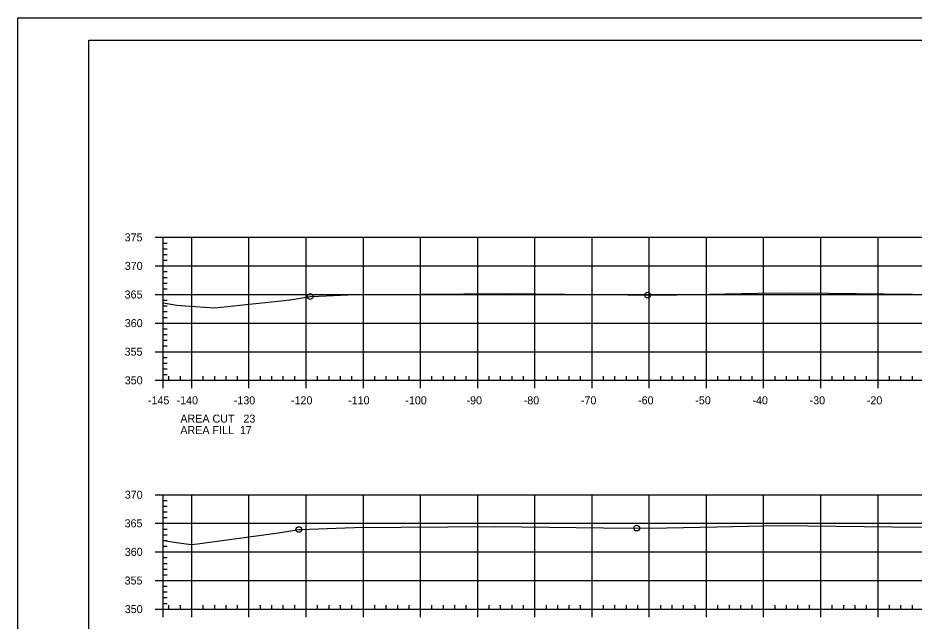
# Model space of a CAD drawing. Extents: x 1359801 to 1362404, y 372415 to 374228.
# Drawn here: x 1360417.1 to 1360573.8, y 373482.5 to 373588 of the extents above; entities that cross this region are included whole.
import ezdxf

# ---------------------------------------------------------------- set-up
doc = ezdxf.new("R2010")
doc.units = 0
for name, color, linetype in [('S_DRG_PT_SYM', 7, 'Continuous'), ('S_MAILBOX', 7, 'Continuous'), ('S_PRIMARY_CTL', 7, 'Continuous'), ('S_SHOULDER', 7, 'Continuous'), ('S_UTL_PT_SYM', 7, 'Continuous'), ('S_WATER_UTILITIES', 7, 'Continuous')]:
    doc.layers.add(name, color=color, linetype=linetype)

msp = doc.modelspace()

# ---------------------------------------------------------------- linework, layer by layer
at = {"layer": 'S_DRG_PT_SYM'}
for points in [[(1360442.53, 373538.12), (1360444.89, 373537.74), (1360446.4, 373537.61), (1360451.48, 373537.26), (1360463.66, 373538.54), (1360464.53, 373538.64), (1360464.75, 373538.68), (1360468.23, 373539.24), (1360469.76, 373539.31), (1360476.11, 373539.6), (1360480.42, 373539.62), (1360502.38, 373539.75), (1360518.08, 373539.6), (1360529.47, 373539.48), (1360546.58, 373539.81), (1360552.23, 373539.92), (1360558.81, 373539.84), (1360578.6, 373539.61)], [(1360442.53, 373496.58), (1360442.59, 373496.57), (1360445.29, 373496.19), (1360447.43, 373495.89), (1360448.54, 373496.04), (1360462.71, 373497.94), (1360465.91, 373498.45), (1360466.24, 373498.5), (1360466.53, 373498.51), (1360474.33, 373498.83), (1360475.99, 373498.84), (1360500.46, 373499.02), (1360519.54, 373498.82), (1360527.68, 373498.74), (1360539.36, 373498.99), (1360550.29, 373499.23), (1360570.05, 373498.99), (1360576.66, 373498.91)]]:
    msp.add_lwpolyline(points, dxfattribs=at)
at = {"layer": 'S_MAILBOX'}
for p, q in [((1360442.53, 373549.6), (1360732.53, 373549.6)), ((1360442.53, 373524.6), (1360442.53, 373549.6)), ((1360447.53, 373524.6), (1360447.53, 373549.6)), ((1360457.53, 373524.6), (1360457.53, 373549.6)), ((1360467.53, 373524.6), (1360467.53, 373549.6)), ((1360477.53, 373524.6), (1360477.53, 373549.6)), ((1360487.53, 373524.6), (1360487.53, 373549.6)), ((1360497.53, 373524.6), (1360497.53, 373549.6)), ((1360507.53, 373524.6), (1360507.53, 373549.6)), ((1360517.53, 373524.6), (1360517.53, 373549.6)), ((1360527.53, 373524.6), (1360527.53, 373549.6)), ((1360537.53, 373524.6), (1360537.53, 373549.6)), ((1360547.53, 373524.6), (1360547.53, 373549.6)), ((1360557.53, 373524.6), (1360557.53, 373549.6)), ((1360567.53, 373524.6), (1360567.53, 373549.6)), ((1360442.53, 373544.6), (1360732.53, 373544.6)), ((1360442.53, 373539.6), (1360732.53, 373539.6)), ((1360442.53, 373534.6), (1360732.53, 373534.6)), ((1360442.53, 373529.6), (1360732.53, 373529.6)), ((1360442.53, 373524.6), (1360732.53, 373524.6)), ((1360442.53, 373504.6), (1360732.53, 373504.6)), ((1360442.53, 373484.6), (1360442.53, 373504.6)), ((1360442.53, 373504.6), (1360732.53, 373504.6)), ((1360442.53, 373484.6), (1360442.53, 373504.6)), ((1360447.53, 373484.6), (1360447.53, 373504.6)), ((1360447.53, 373484.6), (1360447.53, 373504.6)), ((1360457.53, 373484.6), (1360457.53, 373504.6)), ((1360457.53, 373484.6), (1360457.53, 373504.6)), ((1360467.53, 373484.6), (1360467.53, 373504.6)), ((1360467.53, 373484.6), (1360467.53, 373504.6)), ((1360477.53, 373484.6), (1360477.53, 373504.6)), ((1360477.53, 373484.6), (1360477.53, 373504.6)), ((1360487.53, 373484.6), (1360487.53, 373504.6)), ((1360487.53, 373484.6), (1360487.53, 373504.6)), ((1360497.53, 373484.6), (1360497.53, 373504.6)), ((1360497.53, 373484.6), (1360497.53, 373504.6)), ((1360507.53, 373484.6), (1360507.53, 373504.6)), ((1360507.53, 373484.6), (1360507.53, 373504.6)), ((1360517.53, 373484.6), (1360517.53, 373504.6)), ((1360517.53, 373484.6), (1360517.53, 373504.6)), ((1360527.53, 373484.6), (1360527.53, 373504.6)), ((1360527.53, 373484.6), (1360527.53, 373504.6)), ((1360537.53, 373484.6), (1360537.53, 373504.6)), ((1360537.53, 373484.6), (1360537.53, 373504.6)), ((1360547.53, 373484.6), (1360547.53, 373504.6)), ((1360547.53, 373484.6), (1360547.53, 373504.6)), ((1360557.53, 373484.6), (1360557.53, 373504.6)), ((1360557.53, 373484.6), (1360557.53, 373504.6)), ((1360567.53, 373484.6), (1360567.53, 373504.6)), ((1360567.53, 373484.6), (1360567.53, 373504.6)), ((1360442.53, 373499.6), (1360732.53, 373499.6)), ((1360442.53, 373499.6), (1360732.53, 373499.6)), ((1360442.53, 373494.6), (1360732.53, 373494.6)), ((1360442.53, 373494.6), (1360732.53, 373494.6)), ((1360442.53, 373489.6), (1360732.53, 373489.6)), ((1360442.53, 373489.6), (1360732.53, 373489.6)), ((1360442.53, 373484.6), (1360732.53, 373484.6)), ((1360442.53, 373484.6), (1360732.53, 373484.6))]:
    msp.add_line(p, q, dxfattribs=at)
at = {"layer": 'S_SHOULDER'}
msp.add_line((1360417.13, 373587.95), (1360750.46, 373587.95), dxfattribs=at)
for points in [[(1360417.12, 373587.95), (1360750.46, 373587.95), (1360750.46, 373374.61), (1360417.12, 373374.61)], [(1360663.45, 373584.06), (1360663.45, 373574.18), (1360699.18, 373574.18), (1360699.18, 373571.26), (1360722.38, 373571.26), (1360722.38, 373546.93), (1360745.71, 373546.93), (1360745.71, 373378.6), (1360429.53, 373378.6), (1360429.53, 373584.06)]]:
    msp.add_lwpolyline(points, close=True, dxfattribs=at)
for centre in [(1360468.23, 373539.24), (1360527.25, 373539.5), (1360466.24, 373498.5), (1360525.33, 373498.76)]:
    msp.add_circle(centre, 0.5, dxfattribs=at)
at = {"layer": 'S_UTL_PT_SYM'}
for p, q in [((1360429.53, 373584.06), (1360745.71, 373584.06)), ((1360429.53, 373378.6), (1360429.53, 373584.06))]:
    msp.add_line(p, q, dxfattribs=at)
at = {"layer": 'S_WATER_UTILITIES'}
for p, q in [((1360441.13, 373549.6), (1360442.53, 373549.6)), ((1360442.53, 373524.6), (1360442.53, 373549.6)), ((1360442.53, 373548.6), (1360443.23, 373548.6)), ((1360442.53, 373547.6), (1360443.23, 373547.6)), ((1360442.53, 373546.6), (1360443.23, 373546.6)), ((1360442.53, 373545.6), (1360443.23, 373545.6)), ((1360441.13, 373544.6), (1360442.53, 373544.6)), ((1360442.53, 373543.6), (1360443.23, 373543.6)), ((1360442.53, 373542.6), (1360443.23, 373542.6)), ((1360442.53, 373541.6), (1360443.23, 373541.6)), ((1360442.53, 373540.6), (1360443.23, 373540.6)), ((1360441.13, 373539.6), (1360442.53, 373539.6)), ((1360442.53, 373538.6), (1360443.23, 373538.6)), ((1360442.53, 373537.6), (1360443.23, 373537.6)), ((1360442.53, 373536.6), (1360443.23, 373536.6)), ((1360441.13, 373534.6), (1360442.53, 373534.6)), ((1360442.53, 373535.6), (1360443.23, 373535.6)), ((1360442.53, 373533.6), (1360443.23, 373533.6)), ((1360442.53, 373532.6), (1360443.23, 373532.6)), ((1360442.53, 373531.6), (1360443.23, 373531.6)), ((1360441.13, 373529.6), (1360442.53, 373529.6)), ((1360442.53, 373530.6), (1360443.23, 373530.6)), ((1360442.53, 373528.6), (1360443.23, 373528.6)), ((1360442.53, 373527.6), (1360443.23, 373527.6)), ((1360442.53, 373526.6), (1360443.23, 373526.6)), ((1360442.53, 373525.6), (1360443.23, 373525.6)), ((1360442.53, 373524.6), (1360442.53, 373525.3)), ((1360443.53, 373524.6), (1360443.53, 373525.3)), ((1360445.53, 373524.6), (1360445.53, 373525.3)), ((1360449.53, 373524.6), (1360449.53, 373525.3)), ((1360451.53, 373524.6), (1360451.53, 373525.3)), ((1360453.53, 373524.6), (1360453.53, 373525.3)), ((1360455.53, 373524.6), (1360455.53, 373525.3)), ((1360459.53, 373524.6), (1360459.53, 373525.3)), ((1360461.53, 373524.6), (1360461.53, 373525.3)), ((1360463.53, 373524.6), (1360463.53, 373525.3)), ((1360465.53, 373524.6), (1360465.53, 373525.3)), ((1360469.53, 373524.6), (1360469.53, 373525.3)), ((1360471.53, 373524.6), (1360471.53, 373525.3)), ((1360473.53, 373524.6), (1360473.53, 373525.3)), ((1360475.53, 373524.6), (1360475.53, 373525.3)), ((1360479.53, 373524.6), (1360479.53, 373525.3)), ((1360481.53, 373524.6), (1360481.53, 373525.3)), ((1360483.53, 373524.6), (1360483.53, 373525.3)), ((1360485.53, 373524.6), (1360485.53, 373525.3)), ((1360489.53, 373524.6), (1360489.53, 373525.3)), ((1360491.53, 373524.6), (1360491.53, 373525.3)), ((1360493.53, 373524.6), (1360493.53, 373525.3)), ((1360495.53, 373524.6), (1360495.53, 373525.3)), ((1360499.53, 373524.6), (1360499.53, 373525.3)), ((1360501.53, 373524.6), (1360501.53, 373525.3)), ((1360503.53, 373524.6), (1360503.53, 373525.3)), ((1360505.53, 373524.6), (1360505.53, 373525.3)), ((1360509.53, 373524.6), (1360509.53, 373525.3)), ((1360511.53, 373524.6), (1360511.53, 373525.3)), ((1360513.53, 373524.6), (1360513.53, 373525.3)), ((1360515.53, 373524.6), (1360515.53, 373525.3)), ((1360519.53, 373524.6), (1360519.53, 373525.3)), ((1360521.53, 373524.6), (1360521.53, 373525.3)), ((1360523.53, 373524.6), (1360523.53, 373525.3)), ((1360525.53, 373524.6), (1360525.53, 373525.3)), ((1360529.53, 373524.6), (1360529.53, 373525.3)), ((1360531.53, 373524.6), (1360531.53, 373525.3)), ((1360533.53, 373524.6), (1360533.53, 373525.3)), ((1360535.53, 373524.6), (1360535.53, 373525.3)), ((1360539.53, 373524.6), (1360539.53, 373525.3)), ((1360541.53, 373524.6), (1360541.53, 373525.3)), ((1360543.53, 373524.6), (1360543.53, 373525.3)), ((1360545.53, 373524.6), (1360545.53, 373525.3)), ((1360549.53, 373524.6), (1360549.53, 373525.3)), ((1360551.53, 373524.6), (1360551.53, 373525.3)), ((1360553.53, 373524.6), (1360553.53, 373525.3)), ((1360555.53, 373524.6), (1360555.53, 373525.3)), ((1360559.53, 373524.6), (1360559.53, 373525.3)), ((1360561.53, 373524.6), (1360561.53, 373525.3)), ((1360563.53, 373524.6), (1360563.53, 373525.3)), ((1360565.53, 373524.6), (1360565.53, 373525.3)), ((1360569.53, 373524.6), (1360569.53, 373525.3)), ((1360571.53, 373524.6), (1360571.53, 373525.3)), ((1360573.53, 373524.6), (1360573.53, 373525.3)), ((1360441.13, 373524.6), (1360442.53, 373524.6)), ((1360442.53, 373524.6), (1360732.53, 373524.6)), ((1360442.53, 373523.2), (1360442.53, 373524.6)), ((1360447.53, 373523.2), (1360447.53, 373524.6)), ((1360457.53, 373523.2), (1360457.53, 373524.6)), ((1360467.53, 373523.2), (1360467.53, 373524.6)), ((1360477.53, 373523.2), (1360477.53, 373524.6)), ((1360487.53, 373523.2), (1360487.53, 373524.6)), ((1360497.53, 373523.2), (1360497.53, 373524.6)), ((1360507.53, 373523.2), (1360507.53, 373524.6)), ((1360517.53, 373523.2), (1360517.53, 373524.6)), ((1360527.53, 373523.2), (1360527.53, 373524.6)), ((1360537.53, 373523.2), (1360537.53, 373524.6)), ((1360547.53, 373523.2), (1360547.53, 373524.6)), ((1360557.53, 373523.2), (1360557.53, 373524.6)), ((1360567.53, 373523.2), (1360567.53, 373524.6)), ((1360441.13, 373504.6), (1360442.53, 373504.6)), ((1360442.53, 373484.6), (1360442.53, 373504.6)), ((1360442.53, 373503.6), (1360443.23, 373503.6)), ((1360442.53, 373502.6), (1360443.23, 373502.6)), ((1360442.53, 373501.6), (1360443.23, 373501.6)), ((1360442.53, 373500.6), (1360443.23, 373500.6)), ((1360441.13, 373499.6), (1360442.53, 373499.6)), ((1360442.53, 373498.6), (1360443.23, 373498.6)), ((1360442.53, 373497.6), (1360443.23, 373497.6)), ((1360442.53, 373496.6), (1360443.23, 373496.6)), ((1360442.53, 373495.6), (1360443.23, 373495.6)), ((1360441.13, 373494.6), (1360442.53, 373494.6)), ((1360442.53, 373493.6), (1360443.23, 373493.6)), ((1360442.53, 373492.6), (1360443.23, 373492.6)), ((1360442.53, 373491.6), (1360443.23, 373491.6)), ((1360442.53, 373490.6), (1360443.23, 373490.6)), ((1360441.13, 373489.6), (1360442.53, 373489.6)), ((1360442.53, 373488.6), (1360443.23, 373488.6)), ((1360442.53, 373487.6), (1360443.23, 373487.6)), ((1360442.53, 373486.6), (1360443.23, 373486.6)), ((1360441.13, 373484.6), (1360442.53, 373484.6)), ((1360442.53, 373485.6), (1360443.23, 373485.6)), ((1360442.53, 373484.6), (1360442.53, 373485.3)), ((1360442.53, 373484.6), (1360732.53, 373484.6)), ((1360442.53, 373483.2), (1360442.53, 373484.6)), ((1360443.53, 373484.6), (1360443.53, 373485.3)), ((1360445.53, 373484.6), (1360445.53, 373485.3)), ((1360447.53, 373483.2), (1360447.53, 373484.6)), ((1360449.53, 373484.6), (1360449.53, 373485.3)), ((1360451.53, 373484.6), (1360451.53, 373485.3)), ((1360453.53, 373484.6), (1360453.53, 373485.3)), ((1360455.53, 373484.6), (1360455.53, 373485.3)), ((1360457.53, 373483.2), (1360457.53, 373484.6)), ((1360459.53, 373484.6), (1360459.53, 373485.3)), ((1360461.53, 373484.6), (1360461.53, 373485.3)), ((1360463.53, 373484.6), (1360463.53, 373485.3)), ((1360465.53, 373484.6), (1360465.53, 373485.3)), ((1360467.53, 373483.2), (1360467.53, 373484.6)), ((1360469.53, 373484.6), (1360469.53, 373485.3)), ((1360471.53, 373484.6), (1360471.53, 373485.3)), ((1360473.53, 373484.6), (1360473.53, 373485.3)), ((1360475.53, 373484.6), (1360475.53, 373485.3)), ((1360477.53, 373483.2), (1360477.53, 373484.6)), ((1360479.53, 373484.6), (1360479.53, 373485.3)), ((1360481.53, 373484.6), (1360481.53, 373485.3)), ((1360483.53, 373484.6), (1360483.53, 373485.3)), ((1360485.53, 373484.6), (1360485.53, 373485.3)), ((1360487.53, 373483.2), (1360487.53, 373484.6)), ((1360489.53, 373484.6), (1360489.53, 373485.3)), ((1360491.53, 373484.6), (1360491.53, 373485.3)), ((1360493.53, 373484.6), (1360493.53, 373485.3)), ((1360495.53, 373484.6), (1360495.53, 373485.3)), ((1360497.53, 373483.2), (1360497.53, 373484.6)), ((1360499.53, 373484.6), (1360499.53, 373485.3)), ((1360501.53, 373484.6), (1360501.53, 373485.3)), ((1360503.53, 373484.6), (1360503.53, 373485.3)), ((1360505.53, 373484.6), (1360505.53, 373485.3)), ((1360507.53, 373483.2), (1360507.53, 373484.6)), ((1360509.53, 373484.6), (1360509.53, 373485.3)), ((1360511.53, 373484.6), (1360511.53, 373485.3)), ((1360513.53, 373484.6), (1360513.53, 373485.3)), ((1360515.53, 373484.6), (1360515.53, 373485.3)), ((1360517.53, 373483.2), (1360517.53, 373484.6)), ((1360519.53, 373484.6), (1360519.53, 373485.3)), ((1360521.53, 373484.6), (1360521.53, 373485.3)), ((1360523.53, 373484.6), (1360523.53, 373485.3)), ((1360525.53, 373484.6), (1360525.53, 373485.3)), ((1360527.53, 373483.2), (1360527.53, 373484.6)), ((1360529.53, 373484.6), (1360529.53, 373485.3)), ((1360531.53, 373484.6), (1360531.53, 373485.3)), ((1360533.53, 373484.6), (1360533.53, 373485.3)), ((1360535.53, 373484.6), (1360535.53, 373485.3)), ((1360537.53, 373483.2), (1360537.53, 373484.6)), ((1360539.53, 373484.6), (1360539.53, 373485.3)), ((1360541.53, 373484.6), (1360541.53, 373485.3)), ((1360543.53, 373484.6), (1360543.53, 373485.3)), ((1360545.53, 373484.6), (1360545.53, 373485.3)), ((1360547.53, 373483.2), (1360547.53, 373484.6)), ((1360549.53, 373484.6), (1360549.53, 373485.3)), ((1360551.53, 373484.6), (1360551.53, 373485.3)), ((1360553.53, 373484.6), (1360553.53, 373485.3)), ((1360555.53, 373484.6), (1360555.53, 373485.3)), ((1360557.53, 373483.2), (1360557.53, 373484.6)), ((1360559.53, 373484.6), (1360559.53, 373485.3)), ((1360561.53, 373484.6), (1360561.53, 373485.3)), ((1360563.53, 373484.6), (1360563.53, 373485.3)), ((1360565.53, 373484.6), (1360565.53, 373485.3)), ((1360567.53, 373483.2), (1360567.53, 373484.6)), ((1360569.53, 373484.6), (1360569.53, 373485.3)), ((1360571.53, 373484.6), (1360571.53, 373485.3)), ((1360573.53, 373484.6), (1360573.53, 373485.3))]:
    msp.add_line(p, q, dxfattribs=at)

# ---------------------------------------------------------------- texts
at = {"layer": 'S_PRIMARY_CTL'}
for s, p in [('375', (1360435.78, 373548.9)), ('370', (1360435.81, 373543.9)), ('365', (1360435.78, 373538.9)), ('360', (1360435.81, 373533.9)), ('355', (1360435.78, 373528.9)), ('350', (1360435.81, 373523.9)), ('-145', (1360439.86, 373520.4)), ('-140', (1360444.87, 373520.4)), ('-130', (1360454.87, 373520.4)), ('-120', (1360464.87, 373520.4)), ('-110', (1360474.87, 373520.4)), ('-100', (1360484.87, 373520.4)), ('-90', (1360495.57, 373520.4)), ('-80', (1360505.57, 373520.4)), ('-70', (1360515.57, 373520.4)), ('-60', (1360525.57, 373520.4)), ('-50', (1360535.57, 373520.4)), ('-40', (1360545.57, 373520.4)), ('-30', (1360555.57, 373520.4)), ('-20', (1360565.57, 373520.4)), ('AREA CUT   23', (1360445.53, 373517.2)), ('AREA FILL  17', (1360445.53, 373515.2)), ('370', (1360435.81, 373503.9)), ('365', (1360435.78, 373498.9)), ('360', (1360435.81, 373493.9)), ('355', (1360435.78, 373488.9)), ('350', (1360435.81, 373483.9))]:
    msp.add_text(s, height=1.4, dxfattribs=at).set_placement(p)
at = {"layer": 'S_SHOULDER'}
for p in [(1360476.07, 373539.55), (1360474.28, 373498.78)]:
    msp.add_text('+', height=0.1, dxfattribs=at).set_placement(p)

doc.saveas('drawing.dxf')
